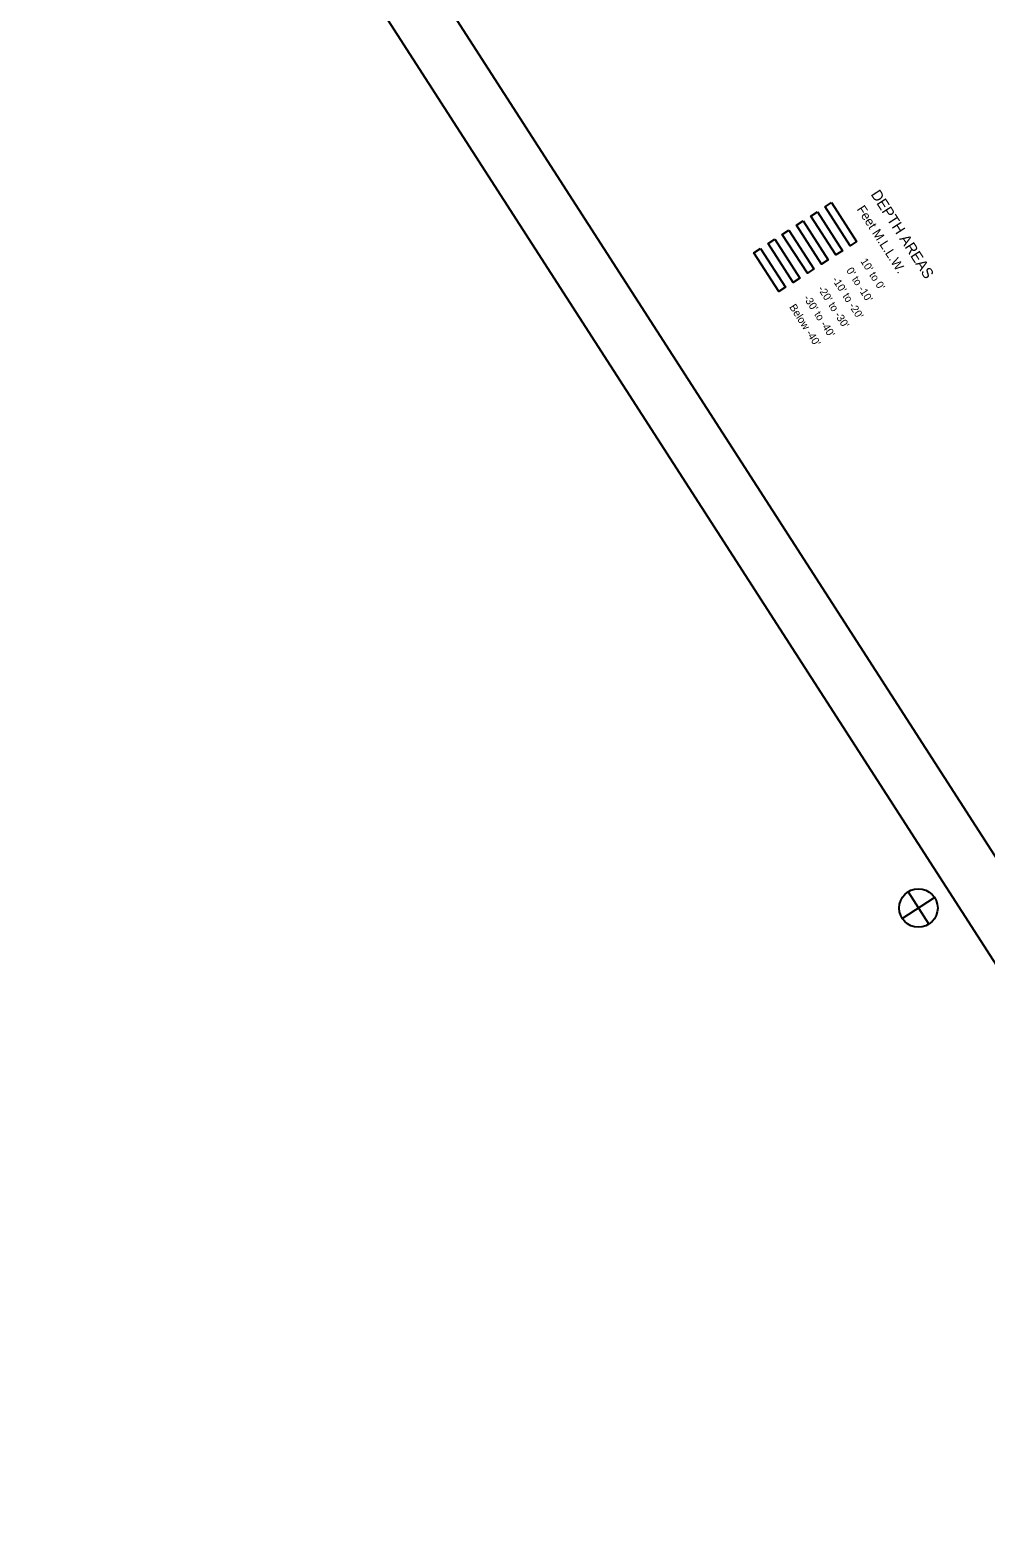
# Model space of a CAD drawing. Extents: x 3937982 to 3958556, y 219448 to 241894.
# Drawn here: x 3938227 to 3943396, y 223893 to 232047 of the extents above; entities that cross this region are included whole.
import ezdxf

# ---------------------------------------------------------------- set-up
doc = ezdxf.new("R2010")
doc.units = 0
for name, color, linetype in [('G-ANNO-NPLT', 7, 'Continuous'), ('V-ANNO-DIMS', 7, 'Continuous'), ('V-ANNO-SYMB', 7, 'Continuous'), ('V-TOPO-DPTH', 7, 'Continuous')]:
    doc.layers.add(name, color=color, linetype=linetype)

msp = doc.modelspace()

# ---------------------------------------------------------------- linework, layer by layer
at = {"layer": 'G-ANNO-NPLT'}
msp.add_lwpolyline([(3938227.293, 235108.722), (3948150.136, 219692.877), (3958310.581, 226232.933), (3948387.738, 241648.778)], close=True, dxfattribs=at)
at = {"layer": 'V-ANNO-DIMS'}
for p, q in [((3942943.463, 227242.936), (3943118.643, 227355.696)), ((3942974.673, 227386.906), (3943087.433, 227211.726))]:
    msp.add_line(p, q, dxfattribs=at)
msp.add_circle((3943031.053, 227299.316), 104.167, dxfattribs=at)
at = {"layer": 'V-ANNO-SYMB'}
msp.add_lwpolyline([(3939234.332, 234121.63), (3948187.407, 220212.388), (3957822.273, 226414.141), (3948869.197, 240323.382), (3939234.332, 234121.63)], dxfattribs=at)
at = {"layer": 'V-TOPO-DPTH'}
for points in [[(3942561.554, 231114.266), (3942696.865, 230904.05), (3942661.129, 230881.047), (3942525.817, 231091.263)], [(3942561.554, 231114.266), (3942696.865, 230904.05), (3942661.129, 230881.047), (3942525.817, 231091.263)], [(3942407.676, 231015.218), (3942542.987, 230805.002), (3942507.25, 230781.999), (3942371.939, 230992.215)], [(3942407.676, 231015.218), (3942542.987, 230805.002), (3942507.25, 230781.999), (3942371.939, 230992.215)], [(3942484.615, 231064.742), (3942619.926, 230854.526), (3942584.189, 230831.523), (3942448.878, 231041.739)], [(3942484.615, 231064.742), (3942619.926, 230854.526), (3942584.189, 230831.523), (3942448.878, 231041.739)], [(3942330.737, 230965.694), (3942466.048, 230755.478), (3942430.311, 230732.475), (3942295, 230942.691)], [(3942330.737, 230965.694), (3942466.048, 230755.478), (3942430.311, 230732.475), (3942295, 230942.691)], [(3942176.858, 230866.646), (3942312.17, 230656.43), (3942276.433, 230633.427), (3942141.122, 230843.643)], [(3942176.858, 230866.646), (3942312.17, 230656.43), (3942276.433, 230633.427), (3942141.122, 230843.643)], [(3942253.797, 230916.17), (3942389.109, 230705.954), (3942353.372, 230682.951), (3942218.061, 230893.167)], [(3942253.797, 230916.17), (3942389.109, 230705.954), (3942353.372, 230682.951), (3942218.061, 230893.167)]]:
    msp.add_lwpolyline(points, close=True, dxfattribs=at)

# ---------------------------------------------------------------- texts
for s, height, rotation, p in [('DEPTH AREAS', 58.35, 302.7685149, (3942771.207, 231159.615)), ('Feet M.L.L.W.', 50, 302.7685032, (3942695.7, 231079.076)), ("10' to 0'", 41.5, 302.7685032, (3942715.674, 230797.231)), ("-10' to -20'", 41.5, 302.7685032, (3942561.795, 230698.183)), ("0' to -10'", 41.5, 302.7685032, (3942638.735, 230747.707)), ("-20' to -30'", 41.5, 302.7685032, (3942484.856, 230648.659)), ("Below -40'", 41.5, 302.7685032, (3942330.978, 230549.611)), ("-30' to -40'", 41.5, 302.7685032, (3942407.917, 230599.135))]:
    msp.add_text(s, height=height, rotation=rotation, dxfattribs=at).set_placement(p)

doc.saveas('drawing.dxf')
